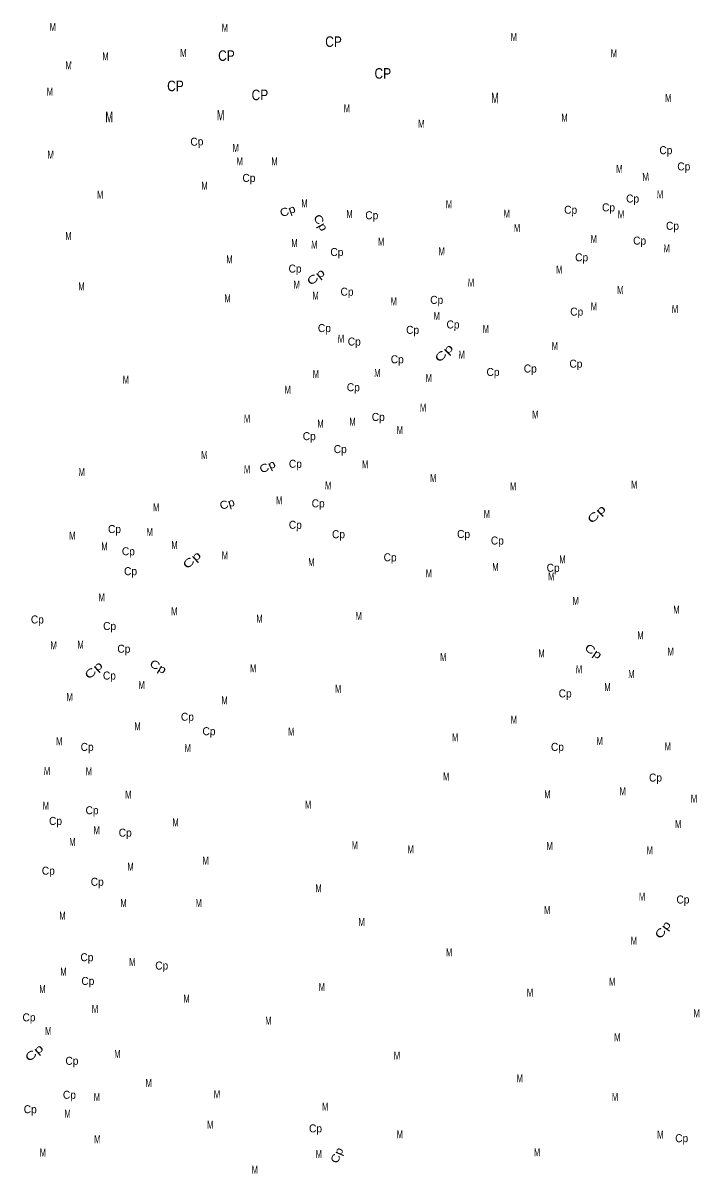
# Model space of a CAD drawing. Extents: x 713577 to 726626, y 7177731 to 7191794.
# Drawn here: x 713679 to 716887, y 7186338 to 7191794 of the extents above; entities that cross this region are included whole.
import ezdxf
from ezdxf.enums import TextEntityAlignment as Align

# ---------------------------------------------------------------- set-up
doc = ezdxf.new("R2010")
doc.units = 0
doc.header["$LTSCALE"] = 15
doc.layers.add('19', color=7, linetype='Continuous')

msp = doc.modelspace()

# ---------------------------------------------------------------- texts
at = {"layer": '19'}
for s, height, rotation, width, p in [('M', 38, 359.549, 0.65, (713820.39, 7191755.46)), ('M', 38, 359.549, 0.65, (714636.83, 7191751.52)), ('M', 38, 359.549, 0.65, (716008.07, 7191708.02)), ('M', 38, 359.549, 0.65, (714439.87, 7191631.85)), ('M', 38, 359.549, 0.65, (714070.47, 7191616.37)), ('M', 38, 359.549, 0.65, (716482.63, 7191630.24)), ('M', 38, 359.549, 0.65, (713895.62, 7191573.19)), ('M', 38, 359.549, 0.65, (713806.76, 7191448.93)), ('M', 50, 359.771, 0.65, (715918.32, 7191412.85)), ('M', 38, 359.549, 0.65, (716740.53, 7191418.7)), ('M', 38, 359.549, 0.65, (715215.67, 7191369.47)), ('M', 50, 359.771, 0.65, (714088.2, 7191322.21)), ('M', 50, 359.771, 0.65, (714616.8, 7191330.6)), ('M', 38, 359.549, 0.65, (716248.32, 7191324.46)), ('M', 38, 359.549, 0.65, (715568.94, 7191295.71)), ('Cp', 38, 2.916, 0.95, (714505.19, 7191211.36)), ('M', 38, 359.549, 0.65, (713810.32, 7191148.9)), ('M', 38, 359.549, 0.65, (714688.11, 7191180.53)), ('Cp', 38, 359.549, 0.95, (716729.3, 7191170.5)), ('M', 38, 359.549, 0.65, (714707.56, 7191117.43)), ('M', 38, 359.549, 0.65, (714872.41, 7191117.37)), ('Cp', 38, 359.549, 0.95, (716814.3, 7191093.5)), ('Cp', 38, 359.549, 0.95, (714751.19, 7191038.86)), ('M', 38, 359.549, 0.65, (716508.34, 7191081.6)), ('M', 38, 4.099, 0.75, (716635.13, 7191044.06)), ('M', 38, 359.549, 0.65, (714540.55, 7191001.57)), ('M', 38, 359.549, 0.65, (714045.35, 7190959.35)), ('Cp', 38, 359.549, 0.95, (716571.47, 7190940.81)), ('M', 38, 359.549, 0.65, (716701.67, 7190960.33)), ('Cp', 38, 20.268, 1.15, (714941.36, 7190884.02)), ('M', 38, 359.549, 0.65, (715014.51, 7190918.37)), ('M', 38, 359.549, 0.65, (715228.49, 7190867.85)), ('M', 38, 359.549, 0.65, (715700.05, 7190913.72)), ('M', 38, 359.549, 0.65, (715974.35, 7190868.76)), ('Cp', 38, 359.549, 0.95, (716277.63, 7190887.63)), ('Cp', 38, 359.549, 0.95, (716457.12, 7190898.89)), ('Cp', 38, 298.918, 1.25, (715075.23, 7190836.46)), ('Cp', 38, 359.549, 0.95, (715334.16, 7190861.52)), ('M', 38, 359.549, 0.65, (716516.3, 7190865.99)), ('M', 38, 359.549, 0.65, (713894.85, 7190763.58)), ('M', 38, 359.639, 0.65, (716023.33, 7190801.71)), ('Cp', 38, 359.549, 0.95, (716760.71, 7190811.41)), ('M', 38, 359.549, 0.65, (714967.21, 7190729.27)), ('M', 38, 359.549, 0.65, (715061.57, 7190721.67)), ('M', 38, 359.549, 0.65, (715378.34, 7190736.12)), ('M', 38, 359.549, 0.65, (716387.33, 7190749.29)), ('Cp', 38, 359.549, 0.95, (716604.85, 7190741.16)), ('M', 38, 359.549, 0.65, (716733.19, 7190704.33)), ('M', 38, 359.549, 0.65, (714658.71, 7190651.61)), ('Cp', 38, 359.549, 0.95, (715168.5, 7190686.86)), ('M', 38, 359.549, 0.65, (715665.47, 7190689.98)), ('Cp', 38, 359.549, 0.95, (716329.71, 7190661.78)), ('Cp', 38, 359.549, 0.95, (714970, 7190608.34)), ('M', 38, 359.549, 0.65, (716223.38, 7190603.76)), ('Cp', 38, 38.862, 1.4, (715080.39, 7190573.16)), ('M', 38, 359.549, 0.65, (715804.84, 7190541.78)), ('M', 38, 359.549, 0.65, (713956.54, 7190523.77)), ('M', 38, 359.549, 0.65, (714977.5, 7190531.93)), ('Cp', 38, 359.549, 0.95, (715216.56, 7190498.57)), ('M', 38, 359.549, 0.65, (716512.97, 7190505.96)), ('M', 38, 359.549, 0.65, (714649.82, 7190467.23)), ('M', 38, 359.549, 0.65, (715067.46, 7190479.8)), ('M', 38, 359.549, 0.65, (715438.17, 7190452.43)), ('Cp', 38, 359.549, 0.95, (715642.1, 7190459.69)), ('M', 38, 359.639, 0.65, (715642.25, 7190382.87)), ('Cp', 38, 359.549, 0.95, (716306.35, 7190403.86)), ('M', 38, 359.549, 0.65, (716387.88, 7190429.18)), ('M', 38, 359.549, 0.65, (716772.65, 7190416.52)), ('Cp', 38, 359.549, 0.95, (715109.25, 7190325.84)), ('Cp', 38, 359.549, 0.95, (715719.33, 7190342.99)), ('M', 38, 359.549, 0.65, (715875.17, 7190321.86)), ('M', 38, 359.549, 0.65, (715188.01, 7190275.67)), ('Cp', 38, 359.549, 0.95, (715527.7, 7190317.25)), ('Cp', 38, 359.549, 0.95, (715250.85, 7190261.88)), ('Cp', 38, 44.193, 1.5, (715689.49, 7190212.8)), ('M', 38, 359.549, 0.65, (716202.34, 7190241.17)), ('Cp', 38, 359.549, 0.95, (715454.91, 7190177.64)), ('M', 38, 359.639, 0.65, (715760.58, 7190199.5)), ('M', 38, 359.549, 0.65, (715068.58, 7190108.02)), ('M', 38, 359.639, 0.65, (715360.55, 7190112.5)), ('Cp', 38, 359.549, 0.95, (715909.22, 7190117.34)), ('Cp', 38, 359.549, 0.95, (716085.92, 7190133.79)), ('Cp', 38, 359.549, 0.95, (716302.62, 7190156.69)), ('M', 38, 359.549, 0.65, (714167.14, 7190081.15)), ('M', 38, 359.549, 0.65, (715604.38, 7190089.35)), ('M', 38, 359.549, 0.65, (714934.92, 7190032.73)), ('Cp', 38, 359.549, 0.95, (715246.42, 7190044.93)), ('M', 38, 359.549, 0.65, (715577.23, 7189947.96)), ('M', 38, 359.549, 0.65, (714742.2, 7189896.19)), ('Cp', 38, 359.549, 0.95, (715364.79, 7189903.85)), ('M', 38, 359.549, 0.65, (716109.88, 7189915.23)), ('M', 38, 359.549, 0.65, (715090.71, 7189871.32)), ('M', 38, 359.549, 0.65, (715242.5, 7189880.92)), ('M', 38, 359.639, 0.65, (715467.28, 7189841.46)), ('Cp', 38, 359.549, 0.95, (715037.27, 7189812.64)), ('M', 38, 359.549, 0.65, (714539.21, 7189723.59)), ('Cp', 38, 359.549, 0.95, (715184.37, 7189751.22)), ('Cp', 38, 25.939, 1.2, (714847.37, 7189670.64)), ('Cp', 38, 359.549, 0.95, (714971.53, 7189681.51)), ('M', 38, 359.549, 0.65, (715302.53, 7189678.68)), ('M', 38, 359.549, 0.65, (713957.69, 7189641.85)), ('M', 38, 359.549, 0.65, (714742.17, 7189655.61)), ('M', 38, 359.549, 0.65, (715625.51, 7189613.39)), ('M', 38, 357.082, 0.7, (715125.9, 7189578.23)), ('M', 38, 359.549, 0.65, (716004.47, 7189574.41)), ('M', 38, 359.549, 0.65, (716579.18, 7189582.65)), ('M', 38, 359.549, 0.65, (714894.65, 7189507.93)), ('M', 38, 359.549, 0.65, (714311.01, 7189474.84)), ('Cp', 38, 17.32, 1.1, (714653.47, 7189492.17)), ('Cp', 38, 359.549, 0.95, (715079.54, 7189493.62)), ('Cp', 38, 44.555, 1.5, (716413.44, 7189448.02)), ('M', 38, 359.549, 0.65, (715880.04, 7189443.43)), ('M', 38, 359.549, 0.65, (713913.25, 7189340.23)), ('Cp', 38, 359.549, 0.95, (714113.25, 7189371.48)), ('M', 38, 359.549, 0.65, (714280.48, 7189357.59)), ('Cp', 38, 359.549, 0.95, (714971.28, 7189391.9)), ('Cp', 38, 359.549, 0.95, (715176.08, 7189347.08)), ('Cp', 38, 359.549, 0.95, (715769.58, 7189347.97)), ('M', 38, 359.549, 0.65, (714065.54, 7189288.86)), ('M', 38, 359.549, 0.65, (714397.77, 7189296.18)), ('Cp', 38, 359.549, 0.95, (715929.77, 7189317.02)), ('Cp', 38, 359.549, 0.95, (714179.1, 7189265.94)), ('Cp', 38, 41.847, 1.45, (714493.17, 7189229.79)), ('M', 38, 359.549, 0.65, (714637.09, 7189246.2)), ('Cp', 38, 359.549, 0.95, (715420.94, 7189237.32)), ('M', 38, 359.549, 0.65, (715047.51, 7189214.41)), ('M', 38, 359.549, 0.65, (715920.52, 7189191.75)), ('Cp', 38, 359.549, 0.95, (716194.4, 7189187.68)), ('M', 38, 359.549, 0.65, (716238.59, 7189227.64)), ('Cp', 38, 359.549, 0.95, (714189.54, 7189171.5)), ('M', 38, 359.549, 0.65, (715604.66, 7189160.8)), ('M', 38, 359.549, 0.65, (716185.51, 7189146.37)), ('M', 38, 359.549, 0.65, (714052.42, 7189047.14)), ('M', 38, 359.549, 0.65, (716301.24, 7189030.25)), ('M', 38, 359.549, 0.65, (714397.16, 7188980.42)), ('M', 38, 359.549, 0.65, (715272.06, 7188958.28)), ('M', 38, 359.549, 0.65, (716779.25, 7188988.96)), ('Cp', 38, 359.549, 0.95, (713747.32, 7188942.2)), ('Cp', 38, 359.549, 0.95, (714090.18, 7188911.15)), ('M', 38, 359.549, 0.65, (714801.17, 7188945.68)), ('M', 38, 359.549, 0.65, (716608.86, 7188867.31)), ('M', 38, 359.549, 0.65, (713824.57, 7188819.12)), ('M', 38, 359.549, 0.65, (713952.48, 7188821.99)), ('Cp', 38, 359.549, 0.95, (714157.71, 7188803.16)), ('Cp', 38, 326.273, 1.3, (716375.06, 7188794.56)), ('M', 38, 359.549, 0.65, (715672.93, 7188763.87)), ('M', 38, 359.905, 0.65, (716139.6, 7188781.15)), ('M', 38, 359.549, 0.65, (716751.99, 7188789.49)), ('Cp', 38, 43.152, 1.45, (714027.16, 7188706.66)), ('Cp', 38, 330.072, 1.25, (714311.37, 7188721.22)), ('M', 38, 359.905, 0.65, (714771.24, 7188710.33)), ('M', 38, 359.549, 0.65, (716317.22, 7188706.2)), ('Cp', 38, 359.639, 0.95, (714089.22, 7188675.97)), ('M', 38, 359.549, 0.65, (714242.24, 7188630.71)), ('M', 38, 359.549, 0.65, (716565.67, 7188682.88)), ('M', 38, 359.549, 0.65, (715174.65, 7188612.85)), ('Cp', 38, 359.549, 0.95, (716251.39, 7188591.07)), ('M', 38, 359.549, 0.65, (716452.18, 7188620.97)), ('M', 38, 359.549, 0.65, (713900.54, 7188573.27)), ('M', 38, 359.549, 0.65, (714635.43, 7188558.11)), ('Cp', 38, 359.639, 0.95, (714459.28, 7188480.31)), ('M', 38, 359.549, 0.65, (714222.67, 7188435.49)), ('Cp', 38, 359.639, 0.95, (714561.57, 7188411.54)), ('M', 38, 359.549, 0.65, (716007.98, 7188465.91)), ('M', 38, 359.905, 0.65, (713851.56, 7188364.15)), ('M', 38, 359.905, 0.65, (714952.07, 7188409.77)), ('M', 38, 359.905, 0.65, (715729.43, 7188382.84)), ('M', 38, 359.549, 0.65, (716415.22, 7188364.64)), ('Cp', 38, 359.549, 0.95, (713983.46, 7188337.13)), ('M', 38, 359.905, 0.65, (714460.93, 7188331.4)), ('Cp', 38, 359.549, 0.95, (716214.82, 7188337.36)), ('M', 38, 359.549, 0.65, (716738.46, 7188339.44)), ('M', 38, 359.905, 0.65, (713793.3, 7188222.36)), ('M', 38, 359.905, 0.65, (713992.06, 7188221.26)), ('M', 38, 359.905, 0.65, (715687.13, 7188196.65)), ('Cp', 38, 359.99, 0.95, (716680.21, 7188191.53)), ('M', 38, 359.905, 0.65, (714179.09, 7188110.22)), ('M', 38, 359.905, 0.65, (716167.35, 7188112.18)), ('M', 38, 359.99, 0.65, (716524.49, 7188126.57)), ('M', 38, 359.99, 0.65, (716862.94, 7188091.22)), ('M', 38, 359.905, 0.65, (713787.9, 7188057.59)), ('Cp', 38, 359.905, 0.95, (714007.01, 7188036.26)), ('M', 38, 359.905, 0.65, (715031.96, 7188063.41)), ('Cp', 38, 359.905, 0.95, (713833.62, 7187985.7)), ('M', 38, 359.905, 0.65, (714403.28, 7187978.41)), ('M', 38, 359.905, 0.65, (714028.78, 7187941.33)), ('Cp', 38, 359.905, 0.95, (714164.24, 7187929.88)), ('M', 38, 359.99, 0.65, (716788.04, 7187970.5)), ('M', 38, 359.905, 0.65, (713913.6, 7187886.19)), ('M', 38, 359.905, 0.65, (715253.16, 7187870.05)), ('M', 38, 359.905, 0.65, (715518.7, 7187850.57)), ('M', 38, 359.905, 0.65, (716178.16, 7187865.95)), ('M', 38, 359.99, 0.65, (716653.1, 7187846.16)), ('M', 38, 1.029, 0.7, (714190.11, 7187767.96)), ('M', 38, 359.905, 0.65, (714545.96, 7187797.17)), ('Cp', 38, 359.905, 0.95, (713799.57, 7187749.49)), ('Cp', 38, 359.905, 0.95, (714031.45, 7187696.72)), ('M', 38, 359.905, 0.65, (715081.44, 7187666.32)), ('M', 38, 359.905, 0.65, (714156.44, 7187595.85)), ('M', 38, 359.905, 0.65, (714512.93, 7187595.26)), ('M', 38, 359.99, 0.65, (716616.44, 7187626.13)), ('Cp', 38, 359.99, 0.95, (716810.41, 7187612.58)), ('M', 38, 359.905, 0.65, (716166.44, 7187562.38)), ('M', 38, 359.905, 0.65, (713866.53, 7187535.55)), ('M', 38, 359.905, 0.65, (715286.02, 7187505.37)), ('Cp', 38, 54.462, 1.35, (716730.14, 7187477.02)), ('M', 38, 359.99, 0.65, (716577.81, 7187416.67)), ('Cp', 38, 359.905, 0.95, (713982.45, 7187338.39)), ('M', 38, 359.905, 0.65, (715700.94, 7187361.38)), ('M', 38, 359.905, 0.65, (713871.22, 7187269.78)), ('M', 38, 359.905, 0.65, (714197.65, 7187315.59)), ('Cp', 38, 359.905, 0.95, (714337.59, 7187299.01)), ('Cp', 38, 359.905, 0.95, (713987.07, 7187225.86)), ('M', 38, 359.99, 0.65, (716474.85, 7187221.73)), ('M', 38, 359.905, 0.65, (713771.38, 7187186.91)), ('M', 38, 359.905, 0.65, (715097.33, 7187197.28)), ('M', 38, 359.905, 0.65, (716084.68, 7187170.45)), ('M', 38, 359.905, 0.65, (714455.43, 7187142.05)), ('Cp', 38, 359.905, 0.95, (713707.69, 7187053.01)), ('M', 38, 359.905, 0.65, (714020.96, 7187093.08)), ('M', 38, 359.99, 0.65, (716875.56, 7187071.9)), ('M', 38, 359.905, 0.65, (714843.48, 7187036.77)), ('M', 38, 359.905, 0.65, (713799.27, 7186987.78)), ('M', 38, 359.99, 0.65, (716499.15, 7186958.81)), ('Cp', 38, 40.715, 1.45, (713744.36, 7186889.38)), ('Cp', 38, 359.905, 0.95, (713911.3, 7186846.67)), ('M', 38, 359.905, 0.65, (714127.04, 7186879.4)), ('M', 38, 359.905, 0.65, (715453.6, 7186870.98)), ('M', 38, 359.905, 0.65, (714275.56, 7186740.66)), ('M', 38, 359.905, 0.65, (716036.24, 7186763.39)), ('Cp', 38, 359.905, 0.95, (713899.49, 7186685.44)), ('M', 38, 359.905, 0.65, (714029.89, 7186674.38)), ('M', 38, 359.905, 0.65, (714599.58, 7186688.19)), ('M', 38, 359.99, 0.65, (716488.22, 7186674.46)), ('Cp', 38, 359.905, 0.95, (713713.7, 7186616.69)), ('M', 38, 359.905, 0.65, (715113.06, 7186629.18)), ('M', 38, 359.905, 0.65, (713890.94, 7186596.07)), ('M', 38, 359.905, 0.65, (714567.61, 7186542.89)), ('Cp', 38, 359.905, 0.95, (715067.11, 7186525.77)), ('M', 38, 359.905, 0.65, (714031.8, 7186474.21)), ('M', 38, 359.905, 0.65, (715467.08, 7186497.8)), ('M', 38, 359.99, 0.65, (716703.26, 7186496.62)), ('Cp', 38, 359.99, 0.95, (716804.47, 7186479.25)), ('M', 38, 359.905, 0.65, (713773.63, 7186411.29)), ('M', 38, 359.905, 0.65, (715082.87, 7186403.54)), ('Cp', 38, 66.789, 1.15, (715185.97, 7186409.65)), ('M', 38, 359.905, 0.65, (716118.37, 7186412.85)), ('M', 38, 359.905, 0.65, (714779.16, 7186329.35))]:
    msp.add_text(s, height=height, rotation=rotation, dxfattribs=dict(at, width=width)).set_placement(p, align=Align.CENTER)
at = {"layer": '19', "width": 0.85}
for p in [(715152.67, 7191679.94), (714644.67, 7191613.64), (715386.59, 7191529.17), (714402.72, 7191469.59), (714803.49, 7191427.05)]:
    msp.add_text('CP', height=50, dxfattribs=at).set_placement(p, align=Align.CENTER)

doc.saveas('drawing.dxf')
